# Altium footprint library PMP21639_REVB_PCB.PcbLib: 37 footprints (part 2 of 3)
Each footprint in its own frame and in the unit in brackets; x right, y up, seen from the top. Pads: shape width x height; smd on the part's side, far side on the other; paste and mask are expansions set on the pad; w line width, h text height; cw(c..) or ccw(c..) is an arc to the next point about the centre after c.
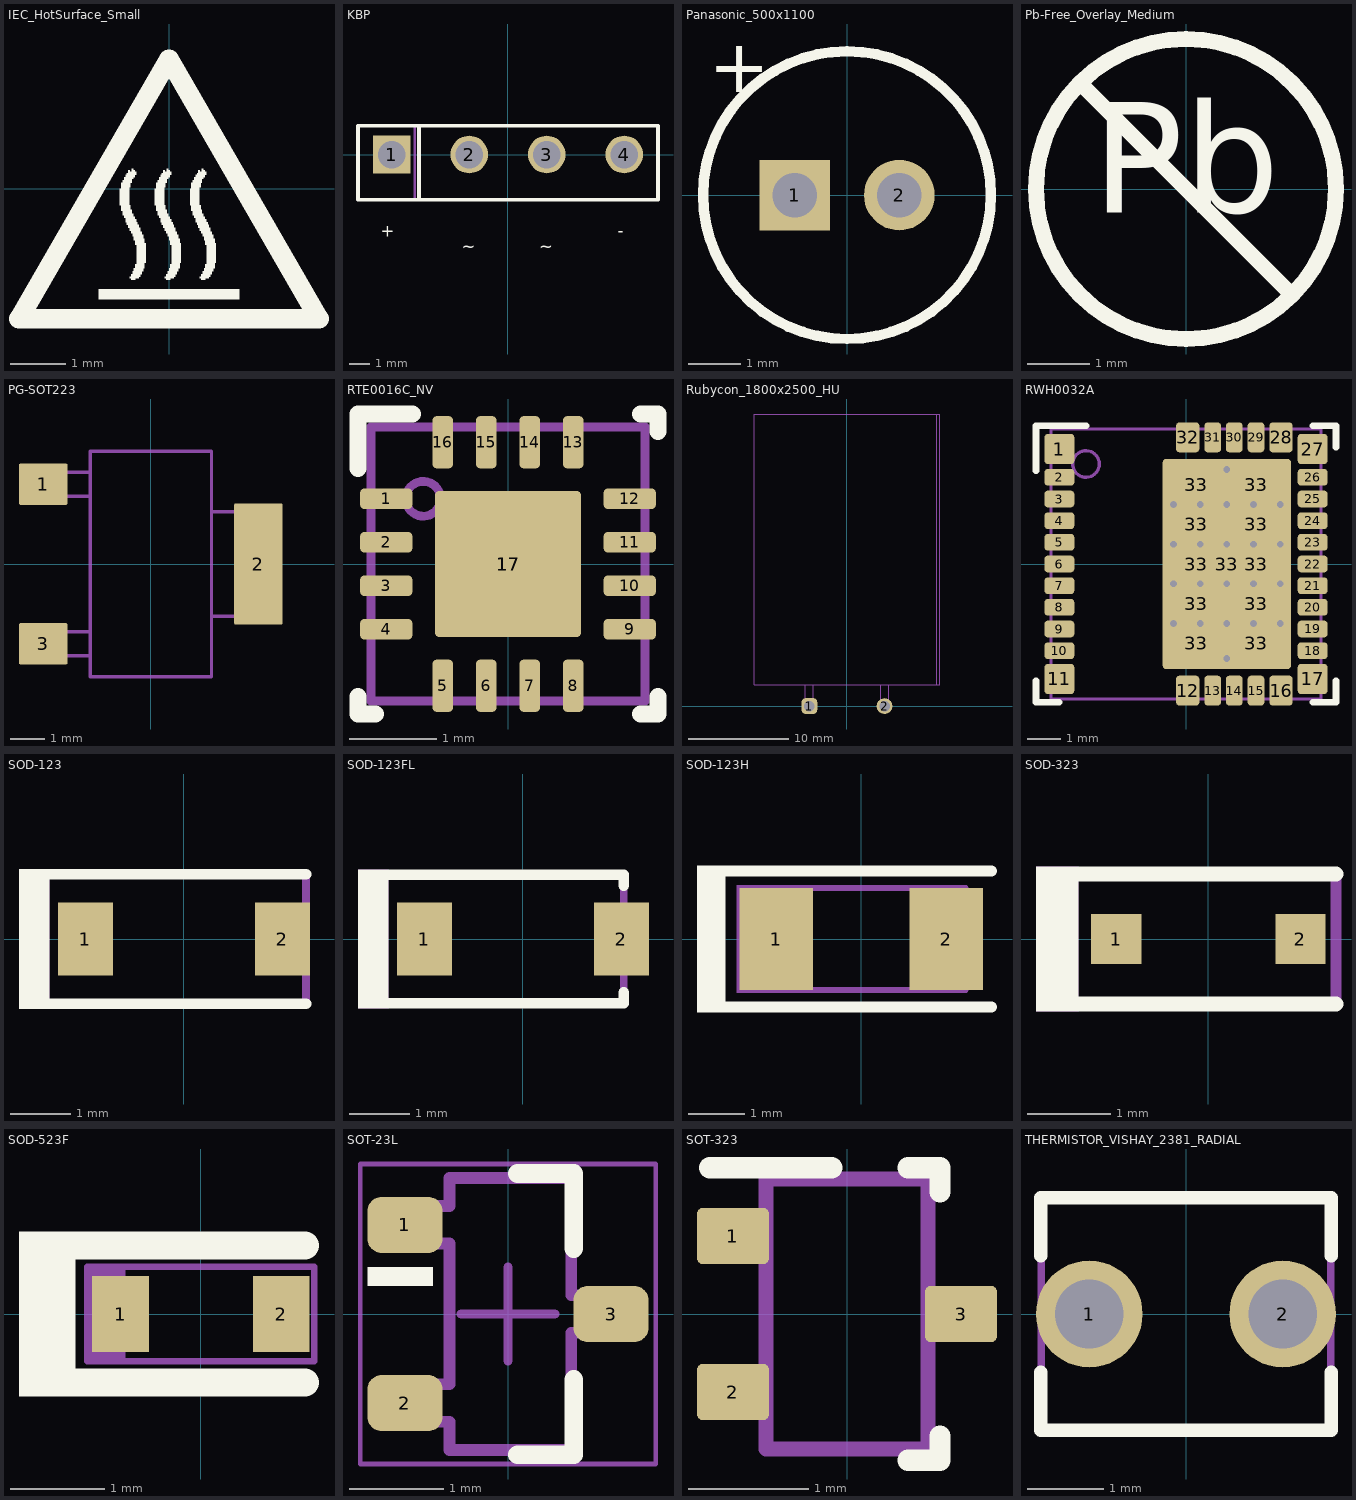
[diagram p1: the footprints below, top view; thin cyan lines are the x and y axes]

## IEC_HotSurface_Small [mm]
Top Overlay:
  drawing of 10 lines, arcs and shapes, not listed

## KBP [mm] "Diodes Inc Bridge Rectifier"
height 13
pads (4):
  rect 1.85x1.85 hole 1.35: 1(-5.715,0)
  round 1.85 hole 1.35: 2(-1.905,0) 3(1.905,0) 4(5.715,0)
Top Overlay:
  lines w0.178: -4.575,-2.23 7.375,-2.23 7.375,1.42 -4.575,1.42 ; -7.375,-2.23 -7.375,1.42 -4.375,1.42 -4.375,-2.23 -7.375,-2.23
  text "~" at 1.53,-4.81 h0.6
  text "~" at -2.28,-4.81 h0.6
  text "-" at 5.4,-4.052 h0.6
  text "+" at -6.26,-4.044 h0.6
Mechanical 5:
  lines w0.127: -4.575,-2.23 7.375,-2.23 7.375,1.42 -4.575,1.42 ; -4.575,-2.23 -7.375,-2.23 -7.375,1.42 -4.575,1.42 ; -4.575,-2.23 -4.575,1.42
  text ".Designator" at -2.825,-0.675 h0.6
3D body "KBP.stp": height 12.91, standoff -4.98, extent -7.375,-2.23 7.375,1.42

## Panasonic_500x1100 [mm] "TH, 2-Leads, Dia 5mm,  Lead Spacing 2mm"
height 12
pads (2):
  rect 1.35x1.35 hole 0.85: 1(-1,0)
  round 1.35 hole 0.85: 2(1,0)
Top Overlay:
  circle w0.2: c0,0 r2.75
  text "+" at -2.638,1.968 h1.02
Mechanical 5:
  circle w0.1: c0,0 r2.75
  text "+" at -3.8,-0.4 h1.02
  text ".Designator" at -1.524,-0.508 h1.02
3D body "ZLJ_500x1100.stp": height 12.51, standoff -3, extent -2.728,-2.745 2.75,2.746

## Pb-Free_Overlay_Medium [mm]
Top Overlay:
  circle w0.254: c0,0 r2.413
  lines w0.254: -1.706,1.706 1.706,-1.706
  text "Pb" at -1.505,-0.961 h3.05

## PG-SOT223 [mm] "SMD, 3-Leads, Body 7x6.5mm"
height 1.8
pads (3):
  rrect8% 1.4x1.2 smd: 1(-3.1,2.3) 3(-3.1,-2.3)
  rrect7% 1.4x3.5 smd: 2(3.1,0)
Mechanical 5:
  lines w0.1: -1.75,-2.65 -2.372,-2.65 -2.536,-2.65 -2.82,-2.65 -2.984,-2.65 -3.5,-2.65 -3.5,-1.95 -2.984,-1.95 -2.82,-1.95 -2.536,-1.95 -2.372,-1.95 -1.75,-1.95 ; -1.75,1.95 -2.372,1.95 -2.536,1.95 -2.82,1.95 -2.984,1.95 -3.5,1.95 -3.5,2.65 -2.984,2.65 -2.82,2.65 -2.536,2.65 -2.372,2.65 -1.75,2.65 ; 1.75,-1.5 2.372,-1.5 2.536,-1.5 2.82,-1.5 2.984,-1.5 3.5,-1.5 3.5,1.5 2.984,1.5 2.82,1.5 2.536,1.5 2.372,1.5 1.75,1.5 ; -1.75,-3.25 -1.75,3.25 1.75,3.25 1.75,-3.25 -1.75,-3.25
  text ".Designator" at -1.4,-0.3 h0.8
3D body "PG-SOT223.stp": height 1.8, standoff 0, extent -3.5,-3.25 3.5,3.25

## RTE0016C_NV [mm] "Texas Insturments"
height 0.8
pads (18):
  rrect42% 0.6x0.24 smd: 1(-1.4,0.75) 2(-1.4,0.25) 3(-1.4,-0.25) 4(-1.4,-0.75) 9(1.4,-0.75) 10(1.4,-0.25) 11(1.4,0.25) 12(1.4,0.75)
  rrect42% 0.24x0.6 smd: 5(-0.75,-1.4) 6(-0.25,-1.4) 7(0.25,-1.4) 8(0.75,-1.4) 13(0.75,1.4) 14(0.25,1.4) 15(-0.25,1.4) 16(-0.75,1.4)
  rrect50% 1.55x1.55 on Top Paste: 17(0,0)
  rrect6% 1.68x1.68 smd paste-0.85: 17(0,0)
Top Overlay:
  lines w0.2: -1.725,-1.525 -1.725,-1.725 -1.525,-1.725 ; -1.725,1.1 -1.725,1.725 -1.1,1.725 ; 1.525,-1.725 1.725,-1.725 1.725,-1.525 ; 1.525,1.725 1.725,1.725 1.725,1.525
Mechanical 5:
  circle w0.1: c-0.975,0.75 r0.2
  lines w0.1: -1.575,-1.575 1.575,-1.575 1.575,1.575 -1.575,1.575 -1.575,-1.575
  text ".Designator" at -1.425,-0.55 h1.4
3D body: height 0.8, standoff 0, extent -1.575,-1.575 1.575,1.575
3D body: height 0.81, standoff 0.5, extent -1.174,0.551 -0.776,0.949

## Rubycon_1800x2500_HU [mm] "TH, 2-Leads, Dia 18mm, Pin Spacing 7.5mm"
height 18.5
pads (2):
  rrect50% 1.575x1.575 hole 1.05: 1(-3.75,0)
  round 1.575 hole 1.05: 2(3.75,0)
Mechanical 5:
  lines w0.1: -4.15,2.15 -4.15,1.2 -4.15,0 ccw(c-3.75,0) -3.35,0 -3.35,1.2 -3.35,2.15 ; 3.35,2.15 3.35,1.2 3.35,0 ccw(c3.75,0) 4.15,0 4.15,1.2 4.15,2.15 ; 8.962,2.15 8.971,2.15 ; 8.962,2.15 -9.25,2.15 -9.25,29.15 8.962,29.15 ; 8.962,2.15 8.962,29.15 ; 8.962,29.15 8.971,29.15 ; 8.971,2.15 8.971,29.15 ; 8.971,2.15 9.26,2.15 9.26,29.15 8.971,29.15
  text "+" at -6,-0.4 h1.02
  text ".Designator" at -1.7,3.3 h1.02
3D body "Rubycon_1800x2500_HU.stp": height 18.5, standoff -4, extent -9.25,-0.399 9.25,29.15

## RWH0032A [mm] "VQFN, 32-Lead, Body 8x8mm"
height 0.9
pads (43):
  rrect22% 0.9x0.9 smd paste-0.07 mask-0.05: 1(-3.8,3.45) 11(-3.8,-3.45) 17(3.8,-3.45) 27(3.8,3.45)
  rrect40% 0.9x0.5 smd paste-0.05 mask-0.05: 2(-3.8,2.6) 3(-3.8,1.95) 4(-3.8,1.3) 5(-3.8,0.65) 6(-3.8,0) 7(-3.8,-0.65) 8(-3.8,-1.3) 9(-3.8,-1.95) 10(-3.8,-2.6) 18(3.8,-2.6) 19(3.8,-1.95) 20(3.8,-1.3) 21(3.8,-0.65) 22(3.8,0) 23(3.8,0.65) 24(3.8,1.3) 25(3.8,1.95) 26(3.8,2.6)
  rrect29% 0.7x0.9 smd paste-0.05 mask-0.05: 12(0.05,-3.8) 16(2.85,-3.8) 28(2.85,3.8) 32(0.05,3.8)
  rrect40% 0.5x0.9 smd paste-0.05 mask-0.05: 13(0.8,-3.8) 14(1.45,-3.8) 15(2.1,-3.8) 29(2.1,3.8) 30(1.45,3.8) 31(0.8,3.8)
  rrect50% 1.6x0.99 on Top Paste: 33(0.314,-2.38) 33(0.314,-1.19) 33(0.314,0) 33(0.314,1.19) 33(0.314,2.38) 33(2.114,-2.38) 33(2.114,-1.19) 33(2.114,0) 33(2.114,1.19) 33(2.114,2.38)
  rrect5% 3.85x6.3 smd paste-2 mask-0.05: 33(1.225,0)
via 1.225,2.835 diameter 0.5 hole 0.2
via 2.025,1.785 diameter 0.5 hole 0.2
via 2.025,0.595 diameter 0.5 hole 0.2
via 2.025,-0.595 diameter 0.5 hole 0.2
via 2.025,-1.785 diameter 0.5 hole 0.2
via 1.225,-2.835 diameter 0.5 hole 0.2
via 1.225,-1.785 diameter 0.5 hole 0.2
via 1.225,-0.595 diameter 0.5 hole 0.2
via 1.225,0.595 diameter 0.5 hole 0.2
via 1.225,1.785 diameter 0.5 hole 0.2
via 2.825,-1.785 diameter 0.5 hole 0.2
via 2.825,-0.595 diameter 0.5 hole 0.2
via 2.825,0.595 diameter 0.5 hole 0.2
via 2.825,1.785 diameter 0.5 hole 0.2
via -0.375,1.785 diameter 0.5 hole 0.2
via -0.375,0.595 diameter 0.5 hole 0.2
via -0.375,-0.595 diameter 0.5 hole 0.2
via -0.375,-1.785 diameter 0.5 hole 0.2
via 0.425,-1.785 diameter 0.5 hole 0.2
via 0.425,-0.595 diameter 0.5 hole 0.2
via 0.425,0.595 diameter 0.5 hole 0.2
via 0.425,1.785 diameter 0.5 hole 0.2
Top Overlay:
  lines w0.2: -4.5,-4.15 -4.5,-3.5 ; -4.5,2.8 -4.5,4.15 -3,4.15 ; -4.45,-4.15 -3.8,-4.15 ; 3.8,-4.15 4.45,-4.15 ; 3.8,4.15 4.45,4.15 ; 4.5,-4.15 4.5,-3.5 ; 4.5,3.5 4.5,4.15
Mechanical 5:
  circle w0.1: c-3,3 r0.4
  lines w0.1: -4.05,-4.05 -4.05,4.05 4.05,4.05 4.05,-4.05 -4.05,-4.05
  text ".Designator" at -1.524,-0.508 h1.02
3D body "RWH0032A.stp": height 0.9, standoff 0, extent -4,-4 4,4

## SOD-123 [mm] "On Semi recommended land pattern"
height 1.35
pads (2):
  rect 0.915x1.22 smd: 1(-1.637,0) 2(1.637,0)
Top Overlay:
  rectangle: -2.743,-1.168 -2.235,1.168
  lines w0.178: -2.413,-1.079 2.032,-1.079 ; -2.413,1.079 2.032,1.079
Mechanical 5:
  rectangle: -2.743,-1.168 -2.235,1.168
  lines w0.127: -2.413,-1.079 2.032,-1.079 2.032,1.079 -2.413,1.079
  text ".Designator" at -1.956,-0.33 h0.76
3D body "SOD-123.stp": height 1.35, standoff 0, extent -1.932,-0.9 1.932,0.9

## SOD-123FL [mm] "Copied from SOD-123"
height 0.991
pads (2):
  rect 0.915x1.22 smd: 1(-1.637,0) 2(1.637,0)
Top Overlay:
  rectangle: -2.743,-1.156 -2.235,1.156
  lines w0.178: -2.438,-1.067 1.676,-1.067 1.676,-0.889 ; -2.438,1.067 1.676,1.067 1.676,0.889
Mechanical 5:
  rectangle: -2.743,-1.156 -2.235,1.156
  lines w0.127: -2.438,-1.067 1.676,-1.067 1.676,1.067 -2.438,1.067
  text ".Designator" at -1.93,-0.229 h0.76
3D body "SOD-123FL.stp": height 1, standoff 0, extent -1.9,-0.9 1.9,0.9

## SOD-123H [mm] "SMT, 2-Leads, Body 3.5x1.6mm"
height 1
pads (2):
  rect 1.3x1.8 smd: 1(-1.5,0) 2(1.5,0)
Top Overlay:
  rectangle: -2.9,-1.3 -2.4,1.3
  lines w0.2: -2.5,-1.2 2.3,-1.2 ; -2.5,1.2 2.3,1.2
Mechanical 5:
  rectangle: -2.2,-0.95 -1.8,0.95
  lines w0.1: -1.85,-0.9 -1.85,0.9 1.85,0.9 1.85,-0.9 -1.85,-0.9
  text ".Designator" at -1.6,-0.4 h0.89
3D body "SOD-123FL.stp": height 1, standoff 0, extent -1.9,-0.9 1.9,0.9

## SOD-323 [mm] "NXP recommended land pattern"
height 1.15
pads (2):
  rect 0.6x0.6 smd paste-0.05: 1(-1.1,0) 2(1.1,0)
Top Overlay:
  rectangle: -2.057,-0.864 -1.549,0.864
  lines w0.178: -1.803,-0.775 0.1,-0.775 1.525,-0.775 ; -1.803,0.775 0.1,0.775 1.525,0.775
Mechanical 5:
  rectangle: -2.057,-0.864 -1.549,0.864
  lines w0.127: -1.803,-0.775 0.1,-0.775 1.525,-0.775 1.525,0.775 0.1,0.775 -1.803,0.775
  text ".Designator" at -1.4,-0.275 h0.76
3D body "SOD-323.stp": height 1.1, standoff 0, extent -1.3,-0.675 1.3,0.675

## SOD-523F [mm] "COMCHIP"
height 0.85
pads (2):
  rect 0.6x0.8 smd paste-0.05: 1(-0.85,0) 2(0.85,0)
Top Overlay:
  rectangle: -1.925,-0.875 -1.325,0.875
  lines w0.3: -1.5,-0.725 1.1,-0.725 ; -1.5,0.725 1.1,0.725
Mechanical 5:
  rectangle: -1.2,-0.5 -0.8,0.5
  lines w0.07: -1.2,-0.5 1.2,-0.5 1.2,0.5 -1.2,0.5 -1.2,-0.5
  text ".Designator" at -0.675,-0.275 h0.46
3D body: height 0.85, standoff 0, extent -0.899,-0.499 0.899,0.499
3D body: height 0.85, standoff 0.84, extent -0.899,-0.499 -0.401,0.499

## SOT-23L [mm] "SOT23, 3-Leads, Body 2.9x1.3mm, Pitch 0.95mm, Lead Span 2.5mm, IPC High Density"
height 1.1
pads (3):
  rrect50% 0.8x0.6 smd: 1(-1.1,0.95) 2(-1.1,-0.95) 3(1.1,0)
Top Overlay:
  rectangle: -1.5,0.3 -0.8,0.5
  lines w0.2: 0.1,-1.5 0.7,-1.5 0.7,-0.7 ; 0.1,1.5 0.7,1.5 0.7,0.7
Mechanical 5:
  lines w0.127: -1.16,-1.15 -1.16,-0.75 -0.625,-0.75 -0.625,0.75 -1.16,0.75 -1.16,1.15 -0.625,1.15 -0.625,1.45 0.675,1.45 0.675,0.2 1.21,0.2 1.21,-0.2 0.675,-0.2 0.675,-1.45 -0.625,-1.45 -0.625,-1.15 -1.16,-1.15
  text ".Designator" at -0.175,1.225 h0.64
Mechanical 15:
  lines w0.05: -1.575,-1.6 1.575,-1.6 1.575,1.6 -1.575,1.6 -1.575,-1.6
  lines w0.1: -0.5,0 0.5,0 ; 0,-0.5 0,0.5
3D body "SW3dPS-sot-3p290x130ll237h100.STEP": height 1, standoff 0, extent -1.16,-1.45 1.21,1.45

## SOT-323 [mm] "Diodes Inc recommended land pattern.  2016-02-24"
height 1.1
pads (3):
  rrect21% 0.6x0.47 smd: 1(-0.95,0.65) 2(-0.95,-0.65) 3(0.95,0)
Top Overlay:
  lines w0.178: -1.143,1.219 -0.127,1.219 ; 0.508,-1.219 0.775,-1.219 0.775,-1.016 ; 0.508,1.219 0.775,1.219 0.775,1.016
Mechanical 5:
  lines w0.127: -1.125,-0.8 -0.975,-0.8 -0.935,-0.8 -0.884,-0.8 -0.725,-0.8 -0.675,-0.8 -0.675,-0.5 -0.725,-0.5 -0.884,-0.5 -0.935,-0.5 -0.975,-0.5 -1.125,-0.5 -1.125,-0.8 ; -1.125,0.5 -0.975,0.5 -0.935,0.5 -0.884,0.5 -0.725,0.5 -0.675,0.5 -0.675,0.8 -0.725,0.8 -0.884,0.8 -0.935,0.8 -0.975,0.8 -1.125,0.8 -1.125,0.5 ; -0.675,-1.125 0.675,-1.125 0.675,1.125 -0.675,1.125 -0.675,-1.125 ; 0.675,-0.15 0.675,0.15 0.725,0.15 0.884,0.15 0.935,0.15 0.975,0.15 1.125,0.15 1.125,-0.15 0.975,-0.15 0.935,-0.15 0.884,-0.15 0.725,-0.15 0.675,-0.15
  text ".Designator" at -0.25,0.9 h0.8
3D body "SC-70.stp": height 1.13, standoff 0.02, extent -1.125,-1.125 1.125,1.125

## THERMISTOR_VISHAY_2381_RADIAL [mm] "Vishay 2381 series thermistors"
height 9
pads (2):
  round 1.4 hole 0.9: 1(-1.27,0) 2(1.27,0)
Top Overlay:
  lines w0.178: -1.905,-0.762 -1.905,-1.524 1.905,-1.524 1.905,-0.762 ; -1.905,0.762 -1.905,1.524 1.905,1.524 1.905,0.762
Mechanical 5:
  lines w0.102: -1.9,-1.5 -1.9,0 -1.9,1.5 0,1.5 1.9,1.5 1.9,0 1.9,-1.5 0,-1.5 -1.9,-1.5
  text ".Designator" at -1.524,-0.508 h1.02
3D body: height 9, standoff 0, extent -1.899,-1.499 1.899,1.499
